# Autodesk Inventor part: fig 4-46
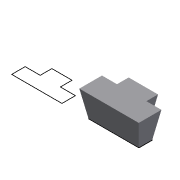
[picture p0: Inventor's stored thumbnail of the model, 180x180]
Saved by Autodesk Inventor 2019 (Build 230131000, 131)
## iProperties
Created: 2004-05
Part Number: fig 4-46
Document SubType Name: Modeling
Designer: CADCIM Technologies
Manufacturer: Standard
Standards Organization: Custom
Density: 1 g/cm^3
Material: Generic
Appearance: Default
Author: CADCIM Technologies
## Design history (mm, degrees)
sketch "Sketch1"
  geometry: L1 (31.783, 34.561)-(31.783, 22.933); L2 (31.783, 22.933)-(16.796, 22.933); L3 (16.796, 22.933)-(16.796, 9.496); L4 (16.796, 9.496)-(66.925, 9.496); L5 (66.925, 9.496)-(66.925, 22.933); L6 (66.925, 22.933)-(51.938, 22.933); L7 (51.938, 22.933)-(51.938, 34.561); L8 (51.938, 34.561)-(31.783, 34.561); L9 (-45.013, 34.561)-(-45.013, 22.933); L10 (-45.013, 22.933)-(-60, 22.933); L11 (-60, 22.933)-(-60, 9.496); L12 (-60, 9.496)-(-9.871, 9.496); L13 (-9.871, 9.496)-(-9.871, 22.933); L14 (-9.871, 22.933)-(-24.858, 22.933); L15 (-24.858, 22.933)-(-24.858, 34.561); L16 (-24.858, 34.561)-(-45.013, 34.561)
  constraints: 32 end point, 10 parallel, 4 equal length, 2 collinear, 2 perpendicular, 2 vertical
extrude "Extrusion2" new body sketch "Sketch1" distance "d2" = 26; taper "d3" = 10 deg
body "Solid2"
